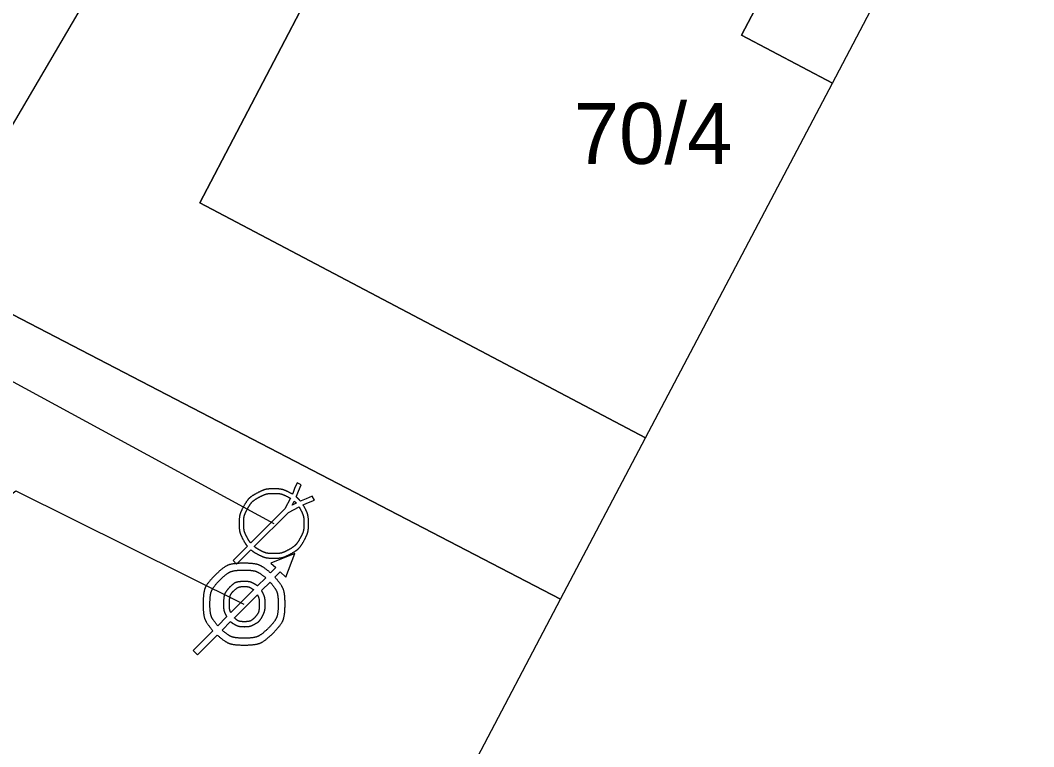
# Model space of a CAD drawing. Extents: x -559654 to -559448, y -1076607 to -1076478.
# Drawn here: x -559474.44 to -559449.48, y -1076580.66 to -1076562.77 of the extents above; entities that cross this region are included whole.
import ezdxf

# ---------------------------------------------------------------- set-up
doc = ezdxf.new("R2010")
doc.units = 0
for name, color, linetype in [('Default', 7, 'Continuous'), ('Kanalizační přípojka', 7, 'Continuous'), ('Odběrné místo', 7, 'Continuous'), ('Odběrné místo na kanalizaci', 7, 'Continuous'), ('Parcela-polygon', 7, 'Continuous'), ('Parcela-text', 7, 'Continuous'), ('Vodovodní přípojka', 7, 'Continuous')]:
    doc.layers.add(name, color=color, linetype=linetype)

msp = doc.modelspace()

# ---------------------------------------------------------------- linework, layer by layer
at = {"layer": 'Default'}
for points in [[(-559468.198, -1076574.312), (-559468.342, -1076574.312), (-559468.482, -1076574.349), (-559468.618, -1076574.422)], [(-559467.779, -1076574.422), (-559467.915, -1076574.349), (-559468.054, -1076574.312), (-559468.198, -1076574.312)], [(-559468.618, -1076574.422), (-559468.755, -1076574.496), (-559468.861, -1076574.601), (-559468.937, -1076574.738)], [(-559468.84, -1076574.794), (-559468.774, -1076574.675), (-559468.681, -1076574.584), (-559468.563, -1076574.52)], [(-559468.563, -1076574.52), (-559468.444, -1076574.456), (-559468.323, -1076574.424), (-559468.198, -1076574.424)], [(-559468.198, -1076574.424), (-559468.073, -1076574.424), (-559467.952, -1076574.456), (-559467.833, -1076574.52)], [(-559467.833, -1076574.52), (-559467.819, -1076574.528), (-559467.805, -1076574.536), (-559467.791, -1076574.544)], [(-559467.741, -1076574.445), (-559467.753, -1076574.437), (-559467.766, -1076574.429), (-559467.779, -1076574.422)], [(-559467.543, -1076574.615), (-559467.575, -1076574.577), (-559467.609, -1076574.543), (-559467.646, -1076574.512)], [(-559468.937, -1076574.738), (-559469.014, -1076574.875), (-559469.052, -1076575.018), (-559469.052, -1076575.166)], [(-559468.94, -1076575.166), (-559468.94, -1076575.038), (-559468.907, -1076574.914), (-559468.84, -1076574.794)], [(-559467.697, -1076574.616), (-559467.68, -1076574.631), (-559467.663, -1076574.648), (-559467.647, -1076574.665)], [(-559467.576, -1076574.759), (-559467.569, -1076574.77), (-559467.562, -1076574.782), (-559467.555, -1076574.794)], [(-559467.555, -1076574.794), (-559467.489, -1076574.914), (-559467.455, -1076575.038), (-559467.455, -1076575.166)], [(-559467.458, -1076574.738), (-559467.465, -1076574.727), (-559467.471, -1076574.717), (-559467.477, -1076574.707)], [(-559467.343, -1076575.166), (-559467.343, -1076575.018), (-559467.382, -1076574.875), (-559467.458, -1076574.738)], [(-559469.052, -1076575.166), (-559469.052, -1076575.315), (-559469.014, -1076575.457), (-559468.939, -1076575.592)], [(-559468.841, -1076575.536), (-559468.907, -1076575.418), (-559468.94, -1076575.295), (-559468.94, -1076575.166)], [(-559467.455, -1076575.166), (-559467.455, -1076575.295), (-559467.488, -1076575.419), (-559467.554, -1076575.536)], [(-559467.456, -1076575.592), (-559467.381, -1076575.457), (-559467.343, -1076575.315), (-559467.343, -1076575.166)], [(-559468.939, -1076575.592), (-559468.912, -1076575.641), (-559468.882, -1076575.686), (-559468.847, -1076575.727)], [(-559468.766, -1076575.646), (-559468.795, -1076575.612), (-559468.82, -1076575.575), (-559468.841, -1076575.536)], [(-559467.554, -1076575.536), (-559467.619, -1076575.654), (-559467.711, -1076575.745), (-559467.828, -1076575.811)], [(-559467.772, -1076575.908), (-559467.637, -1076575.833), (-559467.531, -1076575.728), (-559467.456, -1076575.592)], [(-559468.759, -1076575.815), (-559468.717, -1076575.85), (-559468.672, -1076575.881), (-559468.622, -1076575.908)], [(-559468.567, -1076575.81), (-559468.607, -1076575.788), (-559468.644, -1076575.763), (-559468.678, -1076575.734)], [(-559468.198, -1076575.909), (-559468.326, -1076575.909), (-559468.449, -1076575.876), (-559468.567, -1076575.81)], [(-559467.828, -1076575.811), (-559467.946, -1076575.876), (-559468.069, -1076575.909), (-559468.198, -1076575.909)], [(-559468.622, -1076575.908), (-559468.487, -1076575.983), (-559468.345, -1076576.021), (-559468.198, -1076576.021)], [(-559468.198, -1076576.021), (-559468.05, -1076576.021), (-559467.908, -1076575.983), (-559467.772, -1076575.908)], [(-559468.93, -1076576.145), (-559469.209, -1076576.145), (-559469.447, -1076576.244), (-559469.644, -1076576.44)], [(-559469.525, -1076576.559), (-559469.361, -1076576.395), (-559469.162, -1076576.313), (-559468.93, -1076576.313)], [(-559468.279, -1076576.382), (-559468.463, -1076576.224), (-559468.68, -1076576.145), (-559468.93, -1076576.145)], [(-559468.93, -1076576.313), (-559468.726, -1076576.313), (-559468.549, -1076576.376), (-559468.397, -1076576.502)], [(-559469.644, -1076576.44), (-559469.841, -1076576.637), (-559469.939, -1076576.874), (-559469.939, -1076577.152)], [(-559469.771, -1076577.152), (-559469.771, -1076576.921), (-559469.689, -1076576.723), (-559469.525, -1076576.559)], [(-559468.922, -1076576.595), (-559469.074, -1076576.595), (-559469.197, -1076576.645), (-559469.293, -1076576.746)], [(-559468.655, -1076576.665), (-559468.735, -1076576.618), (-559468.824, -1076576.595), (-559468.922, -1076576.595)], [(-559467.921, -1076577.152), (-559467.921, -1076576.897), (-559468.005, -1076576.676), (-559468.172, -1076576.488)], [(-559469.293, -1076576.746), (-559469.389, -1076576.847), (-559469.437, -1076576.986), (-559469.437, -1076577.165)], [(-559469.291, -1076577.167), (-559469.291, -1076577.005), (-559469.255, -1076576.89), (-559469.182, -1076576.821)], [(-559469.182, -1076576.821), (-559469.109, -1076576.752), (-559469.022, -1076576.718), (-559468.922, -1076576.718)], [(-559468.922, -1076576.718), (-559468.852, -1076576.718), (-559468.788, -1076576.736), (-559468.731, -1076576.772)], [(-559468.731, -1076576.772), (-559468.718, -1076576.78), (-559468.705, -1076576.789), (-559468.694, -1076576.798)], [(-559468.6, -1076576.704), (-559468.617, -1076576.691), (-559468.635, -1076576.678), (-559468.655, -1076576.665)], [(-559468.472, -1076576.864), (-559468.48, -1076576.848), (-559468.489, -1076576.832), (-559468.499, -1076576.817)], [(-559468.29, -1076576.608), (-559468.156, -1076576.762), (-559468.089, -1076576.943), (-559468.089, -1076577.152)], [(-559468.601, -1076576.921), (-559468.601, -1076576.921), (-559468.601, -1076576.922), (-559468.6, -1076576.923)], [(-559468.6, -1076576.923), (-559468.571, -1076576.988), (-559468.556, -1076577.064), (-559468.556, -1076577.151)], [(-559468.41, -1076577.152), (-559468.41, -1076577.045), (-559468.43, -1076576.949), (-559468.472, -1076576.864)], [(-559469.939, -1076577.152), (-559469.939, -1076577.403), (-559469.859, -1076577.621), (-559469.699, -1076577.806)], [(-559469.579, -1076577.686), (-559469.707, -1076577.535), (-559469.771, -1076577.357), (-559469.771, -1076577.152)], [(-559469.437, -1076577.165), (-559469.437, -1076577.259), (-559469.417, -1076577.349), (-559469.375, -1076577.433)], [(-559469.257, -1076577.362), (-559469.28, -1076577.306), (-559469.291, -1076577.241), (-559469.291, -1076577.167)], [(-559468.556, -1076577.151), (-559468.556, -1076577.29), (-559468.591, -1076577.396), (-559468.66, -1076577.472)], [(-559468.476, -1076577.445), (-559468.432, -1076577.359), (-559468.41, -1076577.262), (-559468.41, -1076577.152)], [(-559468.089, -1076577.152), (-559468.089, -1076577.384), (-559468.171, -1076577.582), (-559468.335, -1076577.746)], [(-559468.217, -1076577.865), (-559468.02, -1076577.668), (-559467.921, -1076577.431), (-559467.921, -1076577.152)], [(-559469.375, -1076577.433), (-559469.37, -1076577.444), (-559469.365, -1076577.454), (-559469.359, -1076577.465)], [(-559469.263, -1076577.583), (-559469.242, -1076577.601), (-559469.219, -1076577.618), (-559469.195, -1076577.633)], [(-559468.925, -1076577.585), (-559469.022, -1076577.585), (-559469.103, -1076577.553), (-559469.17, -1076577.489)], [(-559468.66, -1076577.472), (-559468.729, -1076577.547), (-559468.817, -1076577.585), (-559468.925, -1076577.585)], [(-559468.662, -1076577.64), (-559468.582, -1076577.596), (-559468.52, -1076577.531), (-559468.476, -1076577.445)], [(-559468.93, -1076577.991), (-559469.139, -1076577.991), (-559469.32, -1076577.925), (-559469.473, -1076577.793)], [(-559469.195, -1076577.633), (-559469.115, -1076577.682), (-559469.024, -1076577.707), (-559468.924, -1076577.707)], [(-559468.335, -1076577.746), (-559468.5, -1076577.909), (-559468.698, -1076577.991), (-559468.93, -1076577.991)], [(-559468.924, -1076577.707), (-559468.83, -1076577.707), (-559468.743, -1076577.684), (-559468.662, -1076577.64)], [(-559469.593, -1076577.913), (-559469.406, -1076578.077), (-559469.185, -1076578.16), (-559468.93, -1076578.16)], [(-559468.93, -1076578.16), (-559468.651, -1076578.16), (-559468.414, -1076578.061), (-559468.217, -1076577.865)]]:
    msp.add_open_spline(points, degree=2, dxfattribs=at)
at = {"layer": 'Kanalizační přípojka'}
msp.add_lwpolyline([(-559481.775, -1076571.422), (-559477.452, -1076570.144), (-559468.198, -1076575.166)], dxfattribs=at)
at = {"layer": 'Odběrné místo'}
for points in [[(-559468.172, -1076576.488), (-559468.041, -1076576.359), (-559467.904, -1076576.488), (-559467.682, -1076575.902), (-559468.269, -1076576.143), (-559468.151, -1076576.254), (-559468.279, -1076576.382)], [(-559468.397, -1076576.502), (-559468.6, -1076576.704)], [(-559468.694, -1076576.798), (-559469.257, -1076577.362)], [(-559468.499, -1076576.817), (-559468.29, -1076576.608)], [(-559469.17, -1076577.489), (-559468.601, -1076576.921)], [(-559469.359, -1076577.465), (-559469.579, -1076577.686)], [(-559469.473, -1076577.793), (-559469.263, -1076577.583)], [(-559469.699, -1076577.806), (-559470.182, -1076578.29), (-559470.081, -1076578.402)], [(-559470.081, -1076578.402), (-559469.593, -1076577.913)]]:
    msp.add_lwpolyline(points, dxfattribs=at)
at = {"layer": 'Odběrné místo na kanalizaci'}
for points in [[(-559467.646, -1076574.512), (-559467.637, -1076574.494), (-559467.589, -1076574.374), (-559467.524, -1076574.212), (-559467.624, -1076574.166), (-559467.685, -1076574.308), (-559467.731, -1076574.426), (-559467.741, -1076574.445)], [(-559467.791, -1076574.544), (-559467.923, -1076574.802), (-559468.766, -1076575.646)], [(-559467.477, -1076574.707), (-559467.458, -1076574.698), (-559467.34, -1076574.653), (-559467.199, -1076574.591), (-559467.254, -1076574.497), (-559467.405, -1076574.558), (-559467.526, -1076574.606), (-559467.543, -1076574.615)], [(-559468.678, -1076575.734), (-559467.837, -1076574.893), (-559467.576, -1076574.759)], [(-559467.745, -1076574.714), (-559467.697, -1076574.616)], [(-559467.647, -1076574.665), (-559467.745, -1076574.714)], [(-559468.847, -1076575.727), (-559468.859, -1076575.739), (-559468.949, -1076575.828), (-559469.201, -1076576.079), (-559469.113, -1076576.167)], [(-559469.113, -1076576.167), (-559468.861, -1076575.916), (-559468.771, -1076575.827), (-559468.759, -1076575.815)]]:
    msp.add_lwpolyline(points, dxfattribs=at)
at = {"layer": 'Parcela-polygon'}
for p, q in [((-559454.441, -1076564.319), (-559449.485, -1076554.911)), ((-559459.042, -1076573.053), (-559454.441, -1076564.319)), ((-559461.138, -1076577.031), (-559459.042, -1076573.053)), ((-559472.923, -1076599.402), (-559461.138, -1076577.031))]:
    msp.add_line(p, q, dxfattribs=at)
msp.add_lwpolyline([(-559476.74, -1076568.93), (-559481.94, -1076577.8), (-559485.49, -1076575.98), (-559482.14, -1076570.54), (-559468.14, -1076545.12), (-559464.04, -1076547.27)], close=True, dxfattribs=at)
for points in [[(-559449.485, -1076554.911), (-559464.04, -1076547.27), (-559476.74, -1076568.93), (-559461.138, -1076577.031)], [(-559454.441, -1076564.319), (-559456.68, -1076563.14), (-559455.87, -1076561.59), (-559455.1, -1076562), (-559451.87, -1076555.77), (-559460.06, -1076551.47), (-559463.35, -1076557.71), (-559462.38, -1076558.22), (-559463.19, -1076559.76), (-559465.46, -1076558.56), (-559470.02, -1076567.27), (-559459.042, -1076573.053)], [(-559459.042, -1076573.053), (-559470.02, -1076567.27), (-559465.46, -1076558.56), (-559463.19, -1076559.76), (-559462.38, -1076558.22), (-559463.35, -1076557.71), (-559460.06, -1076551.47), (-559451.87, -1076555.77), (-559455.1, -1076562), (-559455.87, -1076561.59), (-559456.68, -1076563.14), (-559454.441, -1076564.319)], [(-559461.138, -1076577.031), (-559476.74, -1076568.93), (-559481.94, -1076577.8), (-559485.49, -1076575.98), (-559493.23, -1076588.57), (-559472.923, -1076599.402)]]:
    msp.add_lwpolyline(points, dxfattribs=at)
at = {"layer": 'Vodovodní přípojka'}
msp.add_lwpolyline([(-559488.697, -1076576.122), (-559488.555, -1076576.199), (-559481.824, -1076579.848), (-559474.55, -1076574.36), (-559468.932, -1076577.152)], dxfattribs=at)

# ---------------------------------------------------------------- texts
at = {"layer": 'Parcela-text'}
msp.add_text('70/4', height=1.5, dxfattribs=at).set_placement((-559460.81, -1076566.31))

doc.saveas('drawing.dxf')
